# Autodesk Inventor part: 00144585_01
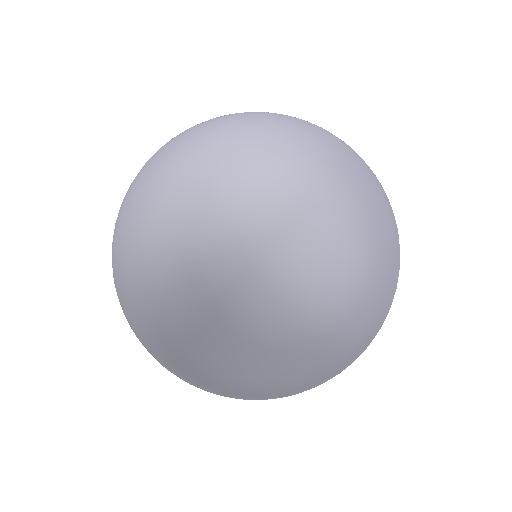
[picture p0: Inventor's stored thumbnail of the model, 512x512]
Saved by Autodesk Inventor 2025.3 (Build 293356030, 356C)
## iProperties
Created: 2021-02
Part Number: 00144585_01
Material: Generico
Document SubType Name: Modeling
Designer: R5800u
Density: 1 g/cm^3
Appearance: Default
Author: TraceParts
Sending System: SolidWorks 2021
Last Author: Albert
Last Saved: 2021-07-28
IsFastener: 1
TYPE: CATASM
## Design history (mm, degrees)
feature "Imported1"
node "Solido1"
